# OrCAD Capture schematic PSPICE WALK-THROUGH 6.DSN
size A
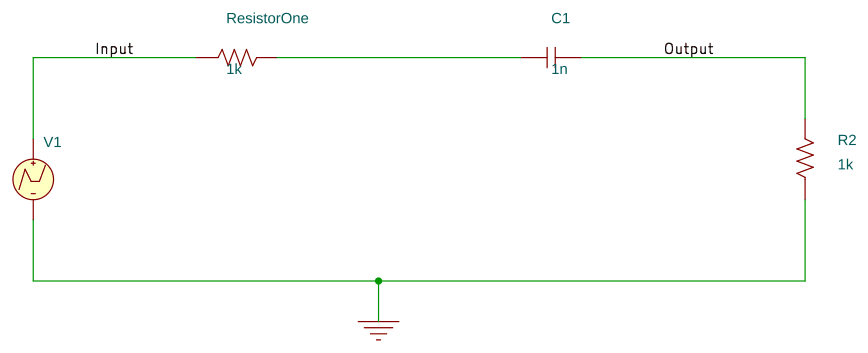
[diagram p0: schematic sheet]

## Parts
C1  1n  [cap196]
R2  1k  [AXRC05]
ResistorOne  1k  [AXRC05]
V1  VPWL_GENERIC

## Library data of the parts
C1 = C
R2 ResistorOne = R
V1 = VPWL_GENERIC: AppProp: No_reps$POINTS_TYPE_PWL$0$0; FIRST_NPAIRS: 1m 2m 2m 0 3m 3m 4m 1m 5m 0; PSpiceTemplate: V^@REFDES %+ %- ?DC|DC @DC| ?AC|AC @AC| PWL ?TSF|TIME_SCALE_FACTOR=@TSF| ?VSF|VALUE_SCALE_FACTOR=@VSF| ?REPEAT_VALUE| \n+ REPEAT FOR @REPEAT_VALUE| \n+ @FIRST_NPAIRS ?SECOND_NPAIRS|\n+ @SECOND_NPAIRS ?THIRD_NPAIRS/\n+ @THIRD_NPAIRS/| ?REPEAT_VALUE| \n+ ENDREPEAT|

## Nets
0: R2.1 V1.2(-)
Input: ResistorOne.1 V1.1(+)
Output: C1.2 R2.2
N00180: C1.1 ResistorOne.2
